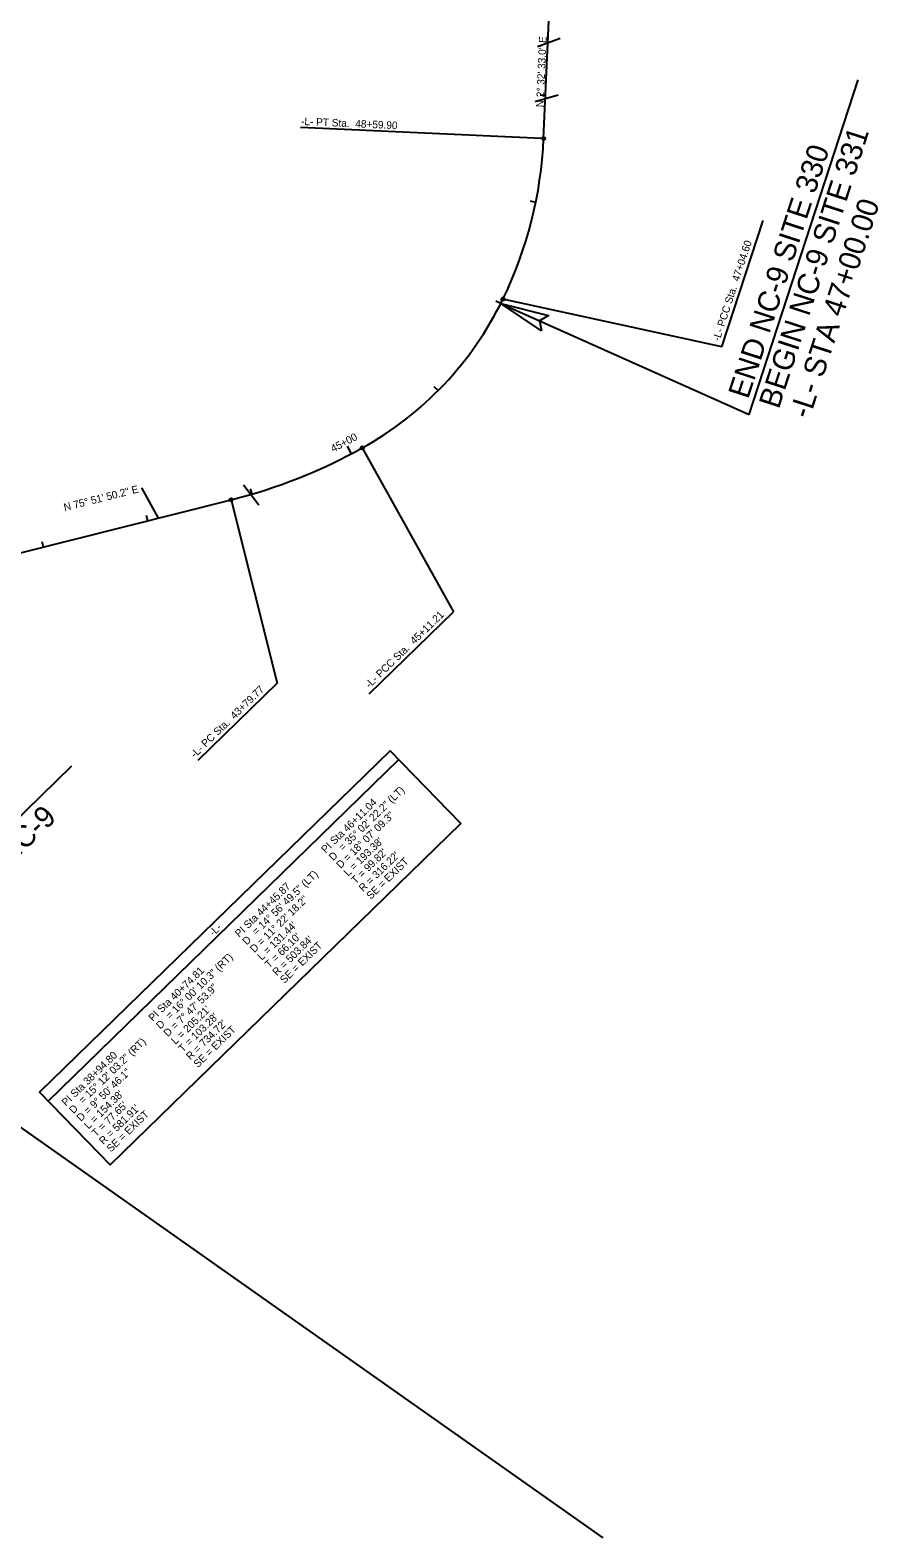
# Model space of a CAD drawing. Extents: x 1019959 to 1023888, y 635993 to 644996.
# Drawn here: x 1021574 to 1022363, y 638025 to 639427 of the extents above; entities that cross this region are included whole.
import ezdxf

# ---------------------------------------------------------------- set-up
doc = ezdxf.new("R2010")
doc.units = 0
for name, color, linetype in [('Cogo Default Point CELL', 7, 'Continuous'), ('COGO Default Point Elevation', 7, 'Continuous'), ('COGO Default Point Number', 7, 'Continuous'), ('Exist Other Culture Well CELL', 7, 'Continuous'), ('Exist Roads EOT', 7, 'Continuous'), ('Exist Structure Minor Pipes CMP 18 Inch Cogo Comment', 7, 'Continuous'), ('Exist Structure Minor Pipes CMP 18 Inch Cogo Number', 7, 'Continuous'), ('Exist Structure Minor Pipes CMP 24 Inch Cogo Number', 7, 'Continuous'), ('Exist Utilities Power Pole CELL', 7, 'Continuous'), ('Exist Utilities Power Pole Cogo Elevation', 7, 'Continuous'), ('Exist Utilities Power Pole Cogo Number', 7, 'Continuous')]:
    doc.layers.add(name, color=color, linetype=linetype)

msp = doc.modelspace()

# ---------------------------------------------------------------- linework, layer by layer
at = {"layer": 'COGO Default Point Elevation'}
for p, q in [((1022052.8, 639366.5), (1022047.8, 639366.7)), ((1022043.7, 639267), (1022038.8, 639268)), ((1022011.1, 639172.8), (1022006.7, 639175)), ((1021952.9, 639092), (1021949.4, 639095.5)), ((1021780, 638995.6), (1021778.6, 639000.4)), ((1021683.2, 638970.8), (1021681.9, 638975.7)), ((1021586.2, 638946.4), (1021585, 638951.3))]:
    msp.add_line(p, q, dxfattribs=at)
at = {"layer": 'COGO Default Point Number'}
msp.add_line((1021872.5, 639033.2), (1021868.8, 639040.3), dxfattribs=at)
at = {"layer": 'Exist Other Culture Well CELL'}
for p, q in [((1022242.2, 639069.7), (1022343.4, 639381)), ((1022011.1, 639172.8), (1022242.2, 639069.7)), ((1021318.2, 638456.2), (1021612.5, 638742.9))]:
    msp.add_line(p, q, dxfattribs=at)
at = {"layer": 'Exist Roads EOT'}
for p, q in [((1022049.5, 639326.5), (1021824.9, 639336.5)), ((1022216.8, 639132.7), (1022255, 639250.2)), ((1022216.8, 639132.7), (1022013.2, 639176.9)), ((1021882.4, 639038.6), (1021967.1, 638886.2)), ((1021760.5, 638990.3), (1021803.4, 638819.9)), ((1021888.9, 638810), (1021967.1, 638886.2)), ((1021803.4, 638819.9), (1021729.5, 638747.9))]:
    msp.add_line(p, q, dxfattribs=at)
for centre in [(1022051, 639326.4), (1022013.2, 639176.9), (1021882.4, 639038.6), (1021760.5, 638990.3)]:
    msp.add_circle(centre, 1.5, dxfattribs=at)
at = {"layer": 'Exist Structure Minor Pipes CMP 18 Inch Cogo Comment'}
msp.add_lwpolyline([(1022049.1, 639147.4), (1022011.1, 639172.8), (1022055.7, 639161.7), (1022047.2, 639156.7)], close=True, dxfattribs=at)
at = {"layer": 'Exist Structure Minor Pipes CMP 18 Inch Cogo Number'}
for p, q in [((1022051, 639326.4), (1022056.8, 639456.5)), ((1021563.6, 638940.7), (1021760.5, 638990.3))]:
    msp.add_line(p, q, dxfattribs=at)
for centre, radius, start, end in [((1021670.1, 639343.3), 381.3, 334.1226, 357.4575), ((1021728.7, 639314.9), 316.2, 299.0831, 334.1226), ((1021637.5, 639478.9), 503.8, 284.136, 299.0831)]:
    msp.add_arc(centre, radius, start, end, dxfattribs=at)
at = {"layer": 'Exist Structure Minor Pipes CMP 24 Inch Cogo Number'}
for p, q in [((1022045.2, 639412), (1022066.5, 639419.7)), ((1022043.2, 639360.7), (1022064.5, 639367)), ((1020572.4, 639106.2), (1022106.2, 638024.9)), ((1021786.2, 638985.3), (1021772.1, 639003.9))]:
    msp.add_line(p, q, dxfattribs=at)
at = {"layer": 'Exist Utilities Power Pole CELL'}
for p, q in [((1022051, 639326.4), (1022056.8, 639456.5)), ((1021563.6, 638940.7), (1021760.5, 638990.3))]:
    msp.add_line(p, q, dxfattribs=at)
for centre, radius, start, end in [((1021670.1, 639343.3), 381.3, 334.1226, 357.4575), ((1021728.7, 639314.9), 316.2, 299.0831, 334.1226), ((1021637.5, 639478.9), 503.8, 284.136, 299.0831)]:
    msp.add_arc(centre, radius, start, end, dxfattribs=at)
at = {"layer": 'Exist Utilities Power Pole Cogo Elevation'}
msp.add_line((1021590.4, 638431.1), (1021916.3, 638748.7), dxfattribs=at)
msp.add_lwpolyline([(1021648.2, 638371.8), (1021974.1, 638689.4), (1021908.3, 638756.9), (1021582.5, 638439.3)], close=True, dxfattribs=at)
at = {"layer": 'Exist Utilities Power Pole Cogo Number'}
msp.add_line((1021677.2, 639001.4), (1021692.9, 638973.3), dxfattribs=at)

# ---------------------------------------------------------------- texts
at = {"layer": 'Cogo Default Point CELL'}
msp.add_text('45+00', height=7, rotation=27.8079, dxfattribs=at).set_placement((1021855.4, 639034.4))
at = {"layer": 'Exist Other Culture Well CELL'}
for s, rotation, p in [('BEGIN NC-9 SITE 331', 71.9892, (1022269.6, 639074.1)), ('END NC-9 SITE 330', 71.9892, (1022241.1, 639083.3)), ('-L- STA 47+00.00', 71.9892, (1022298.1, 639064.8)), ('BEGIN DBB PROJECT NC-9', 44.2601, (1021350.3, 638450.9))]:
    msp.add_text(s, height=20, rotation=rotation, dxfattribs=at).set_placement(p)
at = {"layer": 'Exist Roads EOT'}
for s, rotation, p in [('-L- PT Sta.  48+59.90', 357.4575, (1021825.4, 639339)), ('-L- PCC Sta.  47+04.60', 71.9892, (1022214.5, 639137.5)), ('-L- PCC Sta.  45+11.21', 44.2601, (1021889.2, 638814.7)), ('-L- PC Sta.  43+79.77', 44.2601, (1021726.9, 638749.9))]:
    msp.add_text(s, height=7, rotation=rotation, dxfattribs=at).set_placement(p)
at = {"layer": 'Exist Utilities Power Pole Cogo Elevation'}
for s, p in [('= 35%%d 02\' 22.2" (LT)', (1021864.4, 638663.2)), ('PI Sta 46+11.04', (1021848.4, 638661.2)), ('D = 18%%d 07\' 09.3"', (1021862.3, 638646.9)), ("L = 193.38'", (1021869.3, 638639.7)), ('D', (1021855.4, 638654.1)), ("T = 99.82'", (1021876.3, 638632.6)), ("R = 316.22'", (1021883.3, 638625.4)), ('SE = EXIST', (1021890.3, 638618.2)), ('= 14%%d 56\' 49.5" (LT)', (1021784.1, 638585)), ('PI Sta 44+45.87', (1021768.1, 638583)), ('D = 11%%d 22\' 18.2"', (1021782.1, 638568.7)), ('-L-', (1021744.1, 638584)), ("L = 131.44'", (1021789, 638561.5)), ("T = 66.10'", (1021796, 638554.3)), ('D', (1021775.1, 638575.8)), ("R = 503.84'", (1021803, 638547.2)), ('SE = EXIST', (1021810, 638540)), ('= 16%%d 00\' 10.3" (RT)', (1021703.8, 638506.8)), ('PI Sta 40+74.81', (1021687.8, 638504.7)), ('D = 7%%d 47\' 53.9"', (1021701.8, 638490.4)), ("L = 205.21'", (1021708.8, 638483.3)), ('D', (1021694.8, 638497.6)), ("T = 103.28'", (1021715.7, 638476.1)), ("R = 734.72'", (1021722.7, 638468.9)), ('= 15%%d 12\' 03.2" (RT)', (1021623, 638428.1)), ('SE = EXIST', (1021729.7, 638461.8)), ('PI Sta 38+94.80', (1021607.1, 638426)), ('D = 9%%d 50\' 46.1"', (1021621, 638411.7)), ("L = 154.38'", (1021628, 638404.6)), ('D', (1021614, 638418.9)), ("T = 77.65'", (1021635, 638397.4)), ("R = 581.91'", (1021641.9, 638390.2)), ('SE = EXIST', (1021648.9, 638383.1))]:
    msp.add_text(s, height=7, rotation=44.2601, dxfattribs=at).set_placement(p)
at = {"layer": 'Exist Utilities Power Pole Cogo Number'}
for s, rotation, p in [('N 2%%d 32\' 33.0" E', 87.4575, (1022050.9, 639355.3)), ('N 75%%d 51\' 50.2" E', 14.136, (1021605.9, 638979.8))]:
    msp.add_text(s, height=7, rotation=rotation, dxfattribs=at).set_placement(p)

doc.saveas('drawing.dxf')
